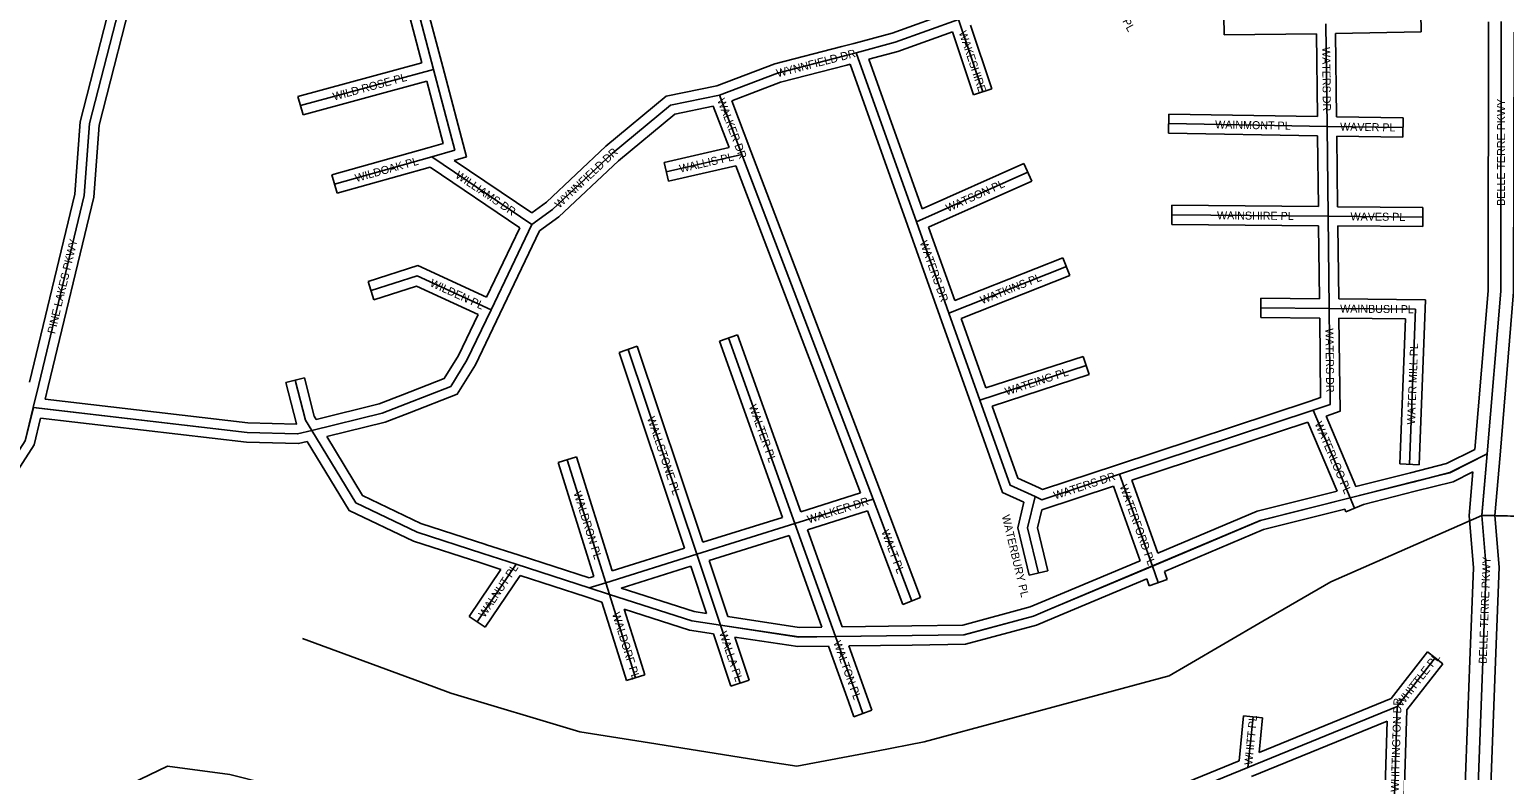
# Model space of a CAD drawing. Extents: x 457167 to 656239, y 1787309 to 1969297.
# Drawn here: x 579932 to 584541, y 1887885 to 1890199 of the extents above; entities that cross this region are included whole.
import ezdxf

# ---------------------------------------------------------------- set-up
doc = ezdxf.new("R2010")
doc.units = 0
for name, color, linetype in [('Level 22', 7, 'Continuous'), ('Level 23', 7, 'Continuous'), ('Level 31', 7, 'Continuous'), ('Level 32', 7, 'Continuous'), ('Level 34', 7, 'Continuous'), ('Level 5', 7, 'Continuous'), ('Level 8', 7, 'Continuous')]:
    doc.layers.add(name, color=color, linetype=linetype)

msp = doc.modelspace()

# ---------------------------------------------------------------- linework, layer by layer
at = {"layer": 'Level 22'}
for p, q in [((584470.225, 1888681.457), (584487.133, 1888873.425)), ((584457.098, 1887810.93), (584472.847, 1888226.538))]:
    msp.add_line(p, q, dxfattribs=at)
for points in [[(584530.76, 1890223.898), (584529.457, 1889381.711), (584487.133, 1888873.425)], [(584472.847, 1888226.538), (584483.905, 1888518.52), (584470.225, 1888681.457)]]:
    msp.add_lwpolyline(points, dxfattribs=at)
at = {"layer": 'Level 23'}
for p, q in [((584510.374, 1888681.374), (584526.979, 1888869.916)), ((584430.079, 1888681.538), (584442.044, 1888817.384)), ((584417.109, 1887811.974), (584432.875, 1888228.053)), ((584497.089, 1887809.885), (584512.819, 1888225.023))]:
    msp.add_line(p, q, dxfattribs=at)
for points in [[(584490.76, 1890223.043), (584489.459, 1889383.406), (584448.168, 1888887.503)], [(584570.711, 1890190.876), (584569.455, 1889380.018), (584526.995, 1888870.106)], [(584432.874, 1888228.052), (584443.841, 1888517.601), (584430.079, 1888681.538)], [(584512.819, 1888225.025), (584523.969, 1888519.439), (584510.374, 1888681.374)]]:
    msp.add_lwpolyline(points, dxfattribs=at)
at = {"layer": 'Level 31'}
for p, q in [((581123.085, 1890347.012), (581194.727, 1890074.501)), ((582835.081, 1890230.49), (582910.643, 1890004.52)), ((583982.794, 1890216.598), (583986.627, 1889896.588)), ((582703.761, 1889598.381), (582515.581, 1890126.76)), ((581194.727, 1890074.501), (580779.159, 1889961.526)), ((582158.444, 1889808.923), (582087.894, 1889994.157)), ((583492.114, 1889905.191), (583986.627, 1889896.588)), ((583986.627, 1889896.588), (583989.898, 1889615.852)), ((583986.627, 1889896.588), (584223.866, 1889892.853)), ((581189.087, 1889801.419), (580885.519, 1889716.58)), ((581502.237, 1889590.239), (581189.087, 1889801.419)), ((582158.444, 1889808.923), (581922.043, 1889754.487)), ((582568.475, 1888732.461), (582158.444, 1889808.923)), ((582703.761, 1889598.381), (583051.669, 1889753.331)), ((581502.237, 1889590.239), (581374.808, 1889323.948)), ((582805.285, 1889313.451), (582703.761, 1889598.381)), ((583501.416, 1889620.081), (583989.898, 1889615.852)), ((583989.898, 1889615.852), (583993.155, 1889327.843)), ((583989.898, 1889615.852), (584285.658, 1889613.458)), ((582805.285, 1889313.451), (583171.941, 1889458.545)), ((582901.749, 1889041.984), (582805.285, 1889313.451)), ((583779.76, 1889329.714), (583993.155, 1889327.843)), ((583993.155, 1889327.843), (584262.839, 1889325.501)), ((584262.839, 1889325.501), (584243.775, 1888841.17)), ((582116.279, 1889235.911), (582324.073, 1888655.856)), ((582017.614, 1888560.103), (581802.947, 1889200.176)), ((582901.749, 1889041.984), (583233.669, 1889149.694)), ((579944.319, 1889018.499), (579961.641, 1889090.828)), ((583942.925, 1889010.121), (583337.636, 1888810.213)), ((583942.925, 1889010.121), (584059.112, 1888736.437)), ((581612.39, 1888855.465), (581733.111, 1888471.218)), ((583337.636, 1888810.213), (583440.755, 1888523.463)), ((584254.481, 1888785.876), (584059.112, 1888736.437)), ((582324.073, 1888655.856), (582568.475, 1888732.461)), ((582568.475, 1888732.461), (582688.7, 1888414.037)), ((584059.112, 1888736.437), (584072.726, 1888704.411)), ((582017.614, 1888560.103), (582324.073, 1888655.856)), ((582324.073, 1888655.856), (582450.269, 1888303.237)), ((581452.718, 1888528.876), (581331.501, 1888348.754)), ((581452.718, 1888528.876), (581348.469, 1888562.541)), ((581680.921, 1888455.324), (581452.718, 1888528.876)), ((581733.111, 1888471.218), (582017.614, 1888560.103)), ((582091.91, 1888338.498), (582017.614, 1888560.103)), ((583440.755, 1888523.463), (583120.863, 1888388.819)), ((583440.755, 1888523.463), (583459.1, 1888471.79)), ((581680.921, 1888455.324), (581733.111, 1888471.218)), ((581744.805, 1888434.831), (581680.921, 1888455.324)), ((581733.111, 1888471.218), (581744.805, 1888434.831)), ((581744.805, 1888434.831), (581806.429, 1888237.978)), ((582152.614, 1888157.285), (582091.91, 1888338.498)), ((582689.759, 1888306.761), (582450.269, 1888303.237)), ((582450.269, 1888303.237), (582519.22, 1888110.371)), ((581806.429, 1888237.978), (581826.021, 1888174.666)), ((584206.055, 1888084.51), (584324.342, 1888236.645)), ((582519.22, 1888110.371), (582536.3, 1888062.701)), ((583739.438, 1887894.145), (584206.055, 1888084.51)), ((584206.055, 1888084.51), (584197.564, 1887804.888)), ((583739.438, 1887894.145), (583755.329, 1888052.297)), ((583516.949, 1887803.307), (583739.438, 1887894.145))]:
    msp.add_line(p, q, dxfattribs=at)
for points in [[(579961.641, 1889090.828), (580103.418, 1889680.723), (580120.416, 1889905.781), (580238.067, 1890364.09)], [(582515.581, 1890126.76), (582636.813, 1890159.61), (582835.081, 1890230.49)], [(582087.894, 1889994.157), (582269.94, 1890062.885), (582478.354, 1890117.016), (582515.581, 1890126.76)], [(581194.727, 1890074.501), (581261.003, 1889822.001), (581189.087, 1889801.419)], [(582087.894, 1889994.157), (581935.498, 1889962.826), (581752.65, 1889811.919), (581566.89, 1889637.018), (581502.237, 1889590.239)], [(581374.808, 1889323.948), (581143.494, 1889429.508), (580999.654, 1889383.617)], [(581374.808, 1889323.948), (581299.118, 1889166.646), (581248.704, 1889084.565), (581108.977, 1889029.938)], [(583993.155, 1889327.843), (583996.708, 1889028.197), (583942.925, 1889010.121)], [(580814.311, 1888946.9), (580794.341, 1888979.304), (580762.154, 1889103.735)], [(583074.484, 1888740.186), (582996.317, 1888775.613), (582901.749, 1889041.984)], [(579245.497, 1888199.936), (579267.455, 1888206.436), (579442.6, 1888314.438), (579710, 1888589.16), (579918.98, 1888914.186), (579944.319, 1889018.499)], [(580814.311, 1888946.9), (580770.083, 1888936.081), (580612.346, 1888940.401), (579944.319, 1889018.499)], [(581108.977, 1889029.938), (581034.182, 1889001.362), (580814.311, 1888946.9)], [(581348.469, 1888562.541), (581143.788, 1888628.772), (580952.198, 1888720.436), (580814.311, 1888946.9)], [(584487.133, 1888873.425), (584370.302, 1888815.106), (584254.481, 1888785.876)], [(583337.636, 1888810.213), (583095.455, 1888730.69), (583074.484, 1888740.186)], [(583074.484, 1888740.186), (583050.758, 1888642.777), (583084.51, 1888501.618)], [(584059.112, 1888736.437), (583778.151, 1888666.076), (583440.755, 1888523.463)], [(582091.91, 1888338.498), (582001.933, 1888352.133), (581744.805, 1888434.831)], [(583120.863, 1888388.819), (583068.98, 1888367.102), (582852.282, 1888308.985), (582689.759, 1888306.761)], [(582450.269, 1888303.237), (582335.455, 1888301.647), (582091.91, 1888338.498)]]:
    msp.add_lwpolyline(points, dxfattribs=at)
at = {"layer": 'Level 32'}
for p, q in [((581152.101, 1890354.64), (581223.742, 1890082.128)), ((581101.408, 1890311.479), (581158.149, 1890095.646)), ((583664.344, 1890242.126), (583665.187, 1890182.131)), ((584279.026, 1890251.472), (584280.013, 1890191.478)), ((582816.343, 1890191.93), (582882.191, 1889995.006)), ((582872.809, 1890212.266), (582939.094, 1890014.034)), ((584013.151, 1890187.091), (584280.013, 1890191.478)), ((584013.151, 1890187.091), (584016.277, 1889926.125)), ((583665.187, 1890182.131), (583953.157, 1890186.177)), ((583953.157, 1890186.177), (583956.259, 1889927.121)), ((581158.149, 1890095.646), (580771.289, 1889990.476)), ((582721.153, 1889638.967), (582554.721, 1890106.281)), ((582675.5, 1889588.316), (582496.554, 1890090.767)), ((581173.394, 1890037.611), (580787.029, 1889932.575)), ((582939.094, 1890014.034), (582882.191, 1889995.006)), ((580787.029, 1889932.575), (580771.289, 1889990.476)), ((582118.151, 1889830.429), (582068.942, 1889959.631)), ((582186.481, 1889819.601), (582126.64, 1889976.716)), ((583492.637, 1889935.187), (583491.594, 1889875.195)), ((583492.637, 1889935.187), (583956.259, 1889927.121)), ((584016.276, 1889926.125), (584224.338, 1889922.85)), ((584224.338, 1889922.85), (584223.394, 1889862.856)), ((583491.594, 1889875.195), (583956.968, 1889867.098)), ((583956.968, 1889867.098), (583959.544, 1889646.116)), ((584016.985, 1889866.104), (584019.554, 1889645.613)), ((584016.986, 1889866.105), (584223.394, 1889862.856)), ((581180.833, 1889830.261), (580877.444, 1889745.473)), ((582118.151, 1889830.429), (581915.312, 1889783.722)), ((582596.512, 1888743.14), (582186.481, 1889819.601)), ((581501.633, 1889626.831), (581259.244, 1889790.291)), ((581928.775, 1889725.251), (581915.312, 1889783.722)), ((582139.712, 1889773.823), (581928.775, 1889725.251)), ((582529.099, 1888751.557), (582139.712, 1889773.822)), ((582721.153, 1889638.968), (583039.464, 1889780.736)), ((583039.464, 1889780.736), (583063.876, 1889725.924)), ((580893.594, 1889687.686), (580877.444, 1889745.473)), ((581183.81, 1889768.792), (580893.594, 1889687.686)), ((581464.002, 1889579.837), (581183.81, 1889768.792)), ((582741.348, 1889582.277), (583063.876, 1889725.924)), ((583501.675, 1889650.08), (583501.157, 1889590.081)), ((583501.675, 1889650.08), (583959.544, 1889646.116)), ((584019.554, 1889645.613), (584285.901, 1889643.457)), ((584285.901, 1889643.457), (584285.416, 1889583.459)), ((582777.026, 1889303.381), (582675.502, 1889588.311)), ((583501.157, 1889590.081), (583960.233, 1889586.106)), ((581464.002, 1889579.838), (581360.463, 1889363.471)), ((581526.006, 1889570.404), (581401.87, 1889310.997)), ((582823.123, 1889352.772), (582741.347, 1889582.277)), ((583960.233, 1889586.106), (583962.812, 1889358.111)), ((584020.243, 1889585.604), (584022.822, 1889357.586)), ((584020.243, 1889585.604), (584285.416, 1889583.459)), ((582823.123, 1889352.772), (583160.902, 1889486.441)), ((583160.902, 1889486.441), (583182.981, 1889430.648)), ((581008.772, 1889355.036), (580990.534, 1889412.199)), ((582843.251, 1889296.208), (583182.981, 1889430.648)), ((583780.024, 1889359.713), (583779.499, 1889299.714)), ((583780.024, 1889359.713), (583962.811, 1889358.111)), ((584022.822, 1889357.586), (584294.034, 1889355.231)), ((584294.034, 1889355.231), (584273.753, 1888839.989)), ((582873.481, 1889031.939), (582777.017, 1889303.405)), ((582920.248, 1889079.527), (582843.251, 1889296.208)), ((583779.499, 1889299.714), (583963.506, 1889298.101)), ((584023.518, 1889297.577), (584231.647, 1889295.769)), ((584231.646, 1889295.769), (584213.798, 1888842.35)), ((582144.522, 1889246.029), (582088.036, 1889225.794)), ((582088.036, 1889225.794), (582285.288, 1888675.167)), ((582144.522, 1889246.029), (582342.598, 1888693.101)), ((581774.504, 1889190.636), (581831.39, 1889209.715)), ((581979.431, 1888579.604), (581774.504, 1889190.636)), ((582036.714, 1888597.501), (581831.39, 1889209.715)), ((582920.248, 1889079.527), (583224.409, 1889178.229)), ((583224.409, 1889178.229), (583242.929, 1889121.157)), ((579981.364, 1889044.372), (579990.817, 1889083.839)), ((580733.109, 1889096.221), (580791.199, 1889111.247)), ((582940.338, 1889022.964), (583242.929, 1889121.157)), ((583933.517, 1889038.608), (583328.229, 1888838.701)), ((583983.207, 1888992.009), (584076.68, 1888771.828)), ((583926.105, 1888972.97), (583376.289, 1888791.383)), ((583926.105, 1888972.97), (584017.785, 1888757.014)), ((581641.012, 1888864.456), (581583.77, 1888846.473)), ((581641.012, 1888864.456), (581752.754, 1888508.786)), ((581583.77, 1888846.473), (581695.419, 1888491.1)), ((584247.121, 1888814.959), (584076.679, 1888771.828)), ((584273.753, 1888839.989), (584213.798, 1888842.35)), ((583319.279, 1888772.607), (583095.351, 1888699.079)), ((583319.279, 1888772.608), (583402.899, 1888540.078)), ((583376.289, 1888791.383), (583458.263, 1888563.432)), ((582342.598, 1888693.101), (582529.099, 1888751.557)), ((582596.543, 1888743.057), (582716.767, 1888424.633)), ((584100.336, 1888716.146), (584045.117, 1888692.673)), ((584100.423, 1888715.943), (584100.336, 1888716.146)), ((584261.842, 1888756.792), (584100.423, 1888715.943)), ((582036.715, 1888597.501), (582285.289, 1888675.166)), ((582362.84, 1888636.565), (582550.417, 1888695.359)), ((582550.417, 1888695.36), (582660.634, 1888403.44)), ((584041.533, 1888701.106), (584045.117, 1888692.673)), ((582362.84, 1888636.566), (582471.285, 1888333.55)), ((581461.938, 1888557.423), (581357.689, 1888591.089)), ((581752.754, 1888508.786), (581979.431, 1888579.604)), ((582055.794, 1888540.601), (582305.531, 1888618.63)), ((582305.532, 1888618.63), (582407.879, 1888332.653)), ((581405.584, 1888512.57), (581339.25, 1888533.991)), ((581681.176, 1888486.762), (581461.921, 1888557.429)), ((582114.527, 1888365.418), (582055.794, 1888540.601)), ((583402.899, 1888540.078), (583109.225, 1888416.469)), ((581405.584, 1888512.569), (581306.612, 1888365.504)), ((581465.004, 1888493.396), (581356.391, 1888332.004)), ((581671.719, 1888426.769), (581465.004, 1888493.395)), ((581681.176, 1888486.762), (581695.419, 1888491.1)), ((581780.93, 1888454.726), (581998.512, 1888522.703)), ((582047.858, 1888375.516), (581998.512, 1888522.703)), ((583113.688, 1888508.595), (583055.333, 1888494.641)), ((583423.114, 1888483.486), (583132.502, 1888361.167)), ((583423.114, 1888483.486), (583430.829, 1888461.752)), ((583487.372, 1888481.827), (583430.829, 1888461.752)), ((583478.491, 1888506.841), (583487.372, 1888481.827)), ((581720.824, 1888411.016), (581671.758, 1888426.756)), ((581720.824, 1888411.016), (581777.799, 1888229.016)), ((582716.767, 1888424.633), (582660.634, 1888403.44)), ((581356.391, 1888332.004), (581306.612, 1888365.504)), ((581790.732, 1888388.546), (581835.06, 1888246.941)), ((582124.167, 1888147.756), (582069.289, 1888311.582)), ((582181.06, 1888166.813), (582135.945, 1888301.492)), ((582689.319, 1888336.759), (582471.285, 1888333.55)), ((582429.242, 1888272.941), (582490.971, 1888100.271)), ((582690.202, 1888276.763), (582492.634, 1888273.856)), ((582492.634, 1888273.856), (582547.469, 1888120.47)), ((584187.296, 1888109.256), (584300.658, 1888255.059)), ((584300.658, 1888255.059), (584348.027, 1888218.229)), ((581777.799, 1888229.016), (581797.362, 1888165.797)), ((581835.089, 1888246.846), (581854.681, 1888183.534)), ((584235.746, 1888073.818), (584348.027, 1888218.229)), ((581854.681, 1888183.534), (581797.362, 1888165.797)), ((582124.167, 1888147.756), (582181.06, 1888166.813)), ((582547.463, 1888120.49), (582564.543, 1888072.819)), ((582490.978, 1888100.251), (582508.058, 1888052.581)), ((582564.543, 1888072.819), (582508.058, 1888052.581)), ((583774.274, 1887940.757), (584187.297, 1888109.256)), ((584235.746, 1888073.818), (584227.55, 1887803.976)), ((583711.393, 1887915.098), (583725.48, 1888055.296)), ((583725.48, 1888055.296), (583785.18, 1888049.297)), ((583750.77, 1887866.367), (584174.669, 1888039.302)), ((583774.274, 1887940.758), (583785.18, 1888049.297)), ((584174.669, 1888039.302), (584168.444, 1887834.305)), ((583505.609, 1887831.082), (583711.393, 1887915.099))]:
    msp.add_line(p, q, dxfattribs=at)
for points in [[(579932.471, 1889097.839), (580073.684, 1889685.388), (580090.699, 1889910.679), (580207.819, 1890366.909)], [(579990.811, 1889083.816), (580133.152, 1889676.059), (580150.132, 1889900.884), (580268.318, 1890361.269)], [(582507.984, 1890155.783), (582627.826, 1890188.257), (582824.982, 1890258.74)], [(582554.721, 1890106.281), (582645.799, 1890130.962), (582816.343, 1890191.929)], [(582079.524, 1890023.063), (582260.846, 1890091.519), (582470.784, 1890146.046), (582507.984, 1890155.783)], [(581223.744, 1890082.117), (581297.47, 1889801.233), (581259.244, 1889790.291)], [(582126.64, 1889976.716), (582279.035, 1890034.251), (582485.923, 1890087.986), (582496.554, 1890090.767)], [(581173.394, 1890037.611), (581224.535, 1889842.769), (581180.833, 1889830.261)], [(582079.524, 1890023.064), (581922.152, 1889990.711), (581732.798, 1889834.433), (581547.735, 1889660.189), (581501.633, 1889626.831)], [(582068.942, 1889959.631), (581948.844, 1889934.941), (581772.502, 1889789.404), (581586.046, 1889613.848), (581526.006, 1889570.405)], [(581360.463, 1889363.471), (581145.412, 1889461.611), (580990.534, 1889412.199)], [(581334.5, 1889309.366), (581141.578, 1889397.406), (581008.772, 1889355.036)], [(581401.842, 1889310.94), (581325.485, 1889152.253), (581268.999, 1889060.288), (581119.901, 1889001.996)], [(581334.5, 1889309.365), (581272.751, 1889181.038), (581228.407, 1889108.842), (581098.054, 1889057.88)], [(583963.506, 1889298.1), (583966.45, 1889049.677), (583933.517, 1889038.608)], [(584023.518, 1889297.577), (584026.965, 1889006.716), (583983.207, 1888992.008)], [(580767.149, 1888966.247), (580766.429, 1888967.414), (580733.109, 1889096.221)], [(580828.359, 1888981.286), (580822.253, 1888991.195), (580791.199, 1889111.247)], [(580767.149, 1888966.247), (580766.873, 1888966.181), (580614.503, 1888970.355), (579981.365, 1889044.372)], [(581098.054, 1889057.88), (581025.189, 1889030.041), (580828.359, 1888981.286)], [(581119.684, 1889001.913), (581043.176, 1888972.682), (580861.185, 1888927.601)], [(583039.452, 1888723.125), (582972.314, 1888753.554), (582873.478, 1889031.947)], [(583086.869, 1888767.511), (583020.32, 1888797.672), (582940.338, 1889022.964)], [(579281.847, 1888180.065), (579461.507, 1888290.851), (579733.603, 1888570.396), (579946.943, 1888902.204), (579967.205, 1888985.618)], [(580800.109, 1888912.539), (580773.294, 1888905.981), (580610.19, 1888910.448), (579967.205, 1888985.618)], [(581339.234, 1888533.997), (581132.648, 1888600.846), (580931.209, 1888697.22), (580800.109, 1888912.54)], [(581357.704, 1888591.084), (581154.929, 1888656.7), (580973.186, 1888743.651), (580861.184, 1888927.601)], [(584448.168, 1888887.504), (584359.811, 1888843.4), (584247.139, 1888814.965)], [(583328.277, 1888838.716), (583097.192, 1888762.836), (583086.859, 1888767.516)], [(584442.044, 1888817.384), (584380.794, 1888786.811), (584261.823, 1888756.787)], [(583039.452, 1888723.125), (583019.896, 1888642.843), (583055.333, 1888494.641)], [(584017.785, 1888757.013), (583768.609, 1888694.614), (583458.263, 1888563.433)], [(583095.351, 1888699.079), (583081.62, 1888642.711), (583113.688, 1888508.595)], [(584041.534, 1888701.106), (583787.692, 1888637.537), (583478.491, 1888506.841)], [(582047.858, 1888375.516), (582008.817, 1888381.433), (581780.93, 1888454.726)], [(583109.279, 1888416.493), (583059.259, 1888395.556), (582848.128, 1888338.931), (582689.349, 1888336.76)], [(582069.289, 1888311.582), (581995.049, 1888322.833), (581790.732, 1888388.546)], [(582407.879, 1888332.653), (582337.504, 1888331.68), (582114.527, 1888365.417)], [(583132.447, 1888361.145), (583078.701, 1888338.648), (582856.437, 1888279.038), (582690.17, 1888276.763)], [(582429.242, 1888272.941), (582333.405, 1888271.616), (582135.946, 1888301.492)], [(579910.369, 1887493.947), (579921.404, 1887514.2), (580103.425, 1887750.031), (580197.321, 1887818.336), (580363.564, 1887898.379), (580558.561, 1887871.834), (580789.924, 1887813.743), (580927.633, 1887620.093)]]:
    msp.add_lwpolyline(points, dxfattribs=at)
at = {"layer": 'Level 5'}
for p, q in [((584470.225, 1888681.457), (584143.325, 1888538.09)), ((583785.488, 1888350.786), (583550.509, 1888214.154)), ((581195.291, 1888146.483), (580785.644, 1888297.498)), ((582234.5, 1887913.118), (581889.851, 1887967.627))]:
    msp.add_line(p, q, dxfattribs=at)
for points in [[(584470.225, 1888681.457), (584828.634, 1888672.765), (585445.16, 1888596.672), (586254.064, 1888670.409), (586562.697, 1888745.101), (586685.865, 1888792.144)], [(584143.325, 1888538.09), (583998.496, 1888474.371), (583785.488, 1888350.786)], [(583550.509, 1888214.154), (583493.197, 1888180.811), (582728.222, 1887974.319), (582578.367, 1887945.526)], [(581889.851, 1887967.627), (581652.033, 1888005.56), (581249.317, 1888126.373), (581195.291, 1888146.483)], [(582578.367, 1887945.526), (582329.564, 1887898.021), (582234.5, 1887913.118)]]:
    msp.add_lwpolyline(points, dxfattribs=at)
at = {"layer": 'Level 8'}
for points in [[(584486.849, 1888873.909), (584369.849, 1888814.907), (584254.848, 1888785.906), (584058.845, 1888736.904), (583777.843, 1888665.901), (583440.84, 1888523.896), (583120.837, 1888388.891), (583068.837, 1888366.89), (582851.834, 1888308.887), (582689.832, 1888306.886), (582449.829, 1888302.885), (582335.828, 1888301.884), (582091.824, 1888338.884), (582001.822, 1888351.884), (581744.817, 1888434.885), (581680.816, 1888454.885), (581452.812, 1888528.886), (581348.81, 1888562.886), (581143.806, 1888628.886), (580951.803, 1888720.887), (580814.798, 1888946.892), (580769.797, 1888935.891), (580612.794, 1888940.891), (579944.784, 1889018.889), (579918.785, 1888913.886)], [(584828.857, 1888672.906), (584469.852, 1888681.905), (584486.849, 1888873.909)]]:
    msp.add_lwpolyline(points, dxfattribs=at)

# ---------------------------------------------------------------- texts
at = {"layer": 'Level 34'}
for s, height, rotation, p in [('WAKEFIELD PL', 25, 298.300972, (583250.139, 1890403.971)), ('WAKESHIRE', 25, 288.488875, (582835.388, 1890190.158)), ('WATERS DR', 25, 270.685144, (583971.16, 1890144.312)), ('WYNNFIELD DR', 25, 14.559142, (582269.83, 1890049.942)), ('WILD ROSE PL', 25, 15.208272, (580883.998, 1889977.075)), ('WALKER DR', 25, 290.850014, (582080.548, 1889978.327)), ('BELLE TERRE PKWY', 25, 89.910494, (584542.367, 1889648.297)), ('WAINMONT PL', 25, 359.002958, (583636.649, 1889890.176)), ('WAVER PL', 25, 359.097875, (584027.106, 1889883.451)), ('WYNNFIELD DR', 25, 43.27455, (581587.504, 1889639.261)), ('WILDOAK PL', 25, 15.613792, (580953.306, 1889722.546)), ('WALLIS PL', 24.9992, 12.967025, (581966.167, 1889751.821)), ('WILLIAMS DR', 25, 326.005075, (581260.727, 1889738.031)), ('WATSON PL', 25, 24.006308, (582802.096, 1889628.495)), ('WAINSHIRE PL', 25, 359.503786, (583642.56, 1889606.358)), ('WAVES PL', 24.9992, 359.536039, (584059.729, 1889602.787)), ('PINE LAKES PKWY', 25, 76.484831, (580012.003, 1889246.883)), ('WATERS DR', 25, 289.611117, (582713.255, 1889534.496)), ('WILDEN PL', 25, 335.470211, (581181.325, 1889398.504)), ('WATKINS PL', 25, 21.589411, (582908.867, 1889340.998)), ('WAINBUSH PL', 25, 359.501972, (584027.262, 1889315.046)), ('WATERS DR', 25, 270.678558, (583981.391, 1889265.741)), ('WATER MILL PL', 25, 87.745081, (584261.15, 1888964.824)), ('WATEING PL', 25, 17.977997, (582984.839, 1889055.806)), ('WALLSTONE PL', 25, 288.539811, (581861.775, 1888985.458)), ('WALTER PL', 25, 289.708575, (582179.41, 1889022.615)), ('WATERLOO PL', 25, 293.002283, (583947.051, 1888968.415)), ('WATERS DR', 25, 18.177867, (583136.957, 1888731.161)), ('WALDRON PL', 25, 287.440753, (581631.656, 1888752.445)), ('WATERFORD PL', 25, 289.778569, (583337.785, 1888772.861)), ('WALKER DR', 25, 17.402436, (582367.062, 1888656.231)), ('WATERBURY PL', 25, 283.446878, (582970.07, 1888680.171)), ('WALT PL', 25, 290.684047, (582593.364, 1888631.154)), ('BELLE TERRE PKWY', 25, 87.830317, (584485.018, 1888217.679)), ('WALNUT PL', 25, 56.059556, (581354.209, 1888360.109)), ('WALDORF PL', 25, 287.193936, (581752.225, 1888374.505)), ('WALLA PL', 25, 288.519186, (582086.7, 1888314.701)), ('WALTON PL', 25, 289.671664, (582443.553, 1888284.897)), ('WHITTLE PL', 25, 52.133658, (584220.258, 1888082.414)), ('WHITTINGTON DR', 25, 88.259689, (584210.459, 1887817.764)), ('WHITT PL', 25, 84.26105, (583752.688, 1887900.991))]:
    msp.add_text(s, height=height, rotation=rotation, dxfattribs=at).set_placement(p)

doc.saveas('drawing.dxf')
